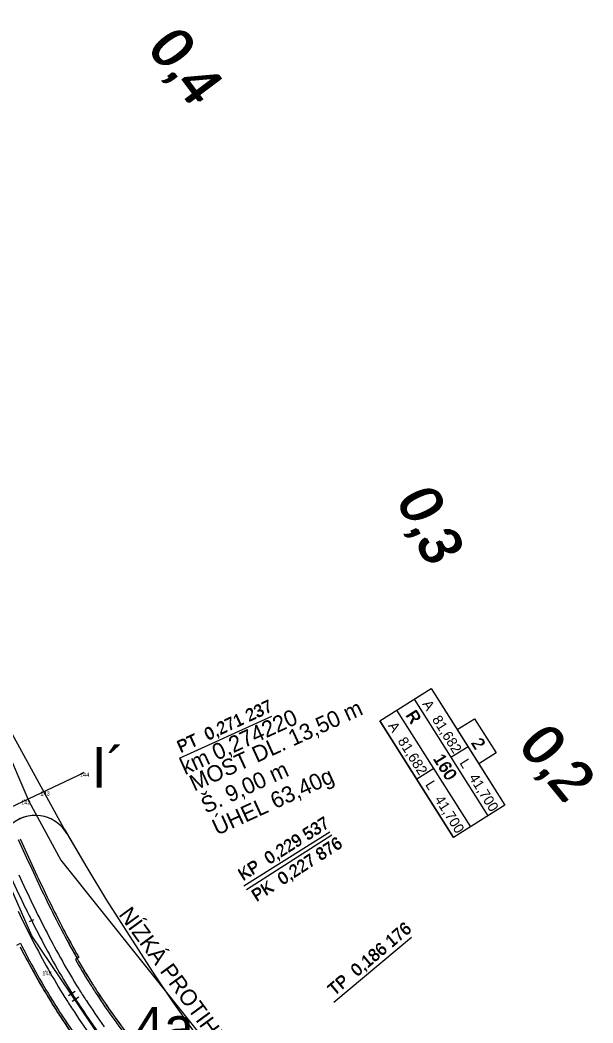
# Model space of a CAD drawing. Extents: x -606444 to -604546, y -1158114 to -1156869.
# Drawn here: x -605105.4 to -604964.2, y -1157370.5 to -1157123.3 of the extents above; entities that cross this region are included whole.
import ezdxf

# ---------------------------------------------------------------- set-up
doc = ezdxf.new("R2010")
doc.units = 0
for name, color, linetype in [('B_TRAM', 7, 'Continuous'), ('B_VOZ', 7, 'Continuous'), ('B_ZELEN', 7, 'Continuous'), ('geofyzikální profily_předběžný GTP', 7, 'Continuous'), ('NS_VB', 7, 'Continuous'), ('NS_VB_OBJ', 7, 'Continuous'), ('NS_VB_POP', 7, 'Continuous'), ('OSA', 7, 'Continuous'), ('OSAPOP', 7, 'Continuous'), ('podélný profil trasou tramvaje', 7, 'Continuous'), ('Sondy 2', 7, 'Continuous'), ('stabilitní profily_předběžný GTP', 7, 'Continuous')]:
    doc.layers.add(name, color=color, linetype=linetype)

msp = doc.modelspace()

# ---------------------------------------------------------------- linework, layer by layer
for p, q in [((-605089.73, -1157308.8), (-605089.83, -1157308.7)), ((-605089.73, -1157308.8), (-605089.83, -1157308.9)), ((-605089.73, -1157308.8), (-605089.63, -1157308.7)), ((-605089.73, -1157308.8), (-605089.63, -1157308.9)), ((-605099.46, -1157313.42), (-605099.56, -1157313.32)), ((-605099.46, -1157313.42), (-605099.56, -1157313.52)), ((-605099.46, -1157313.42), (-605099.36, -1157313.32)), ((-605099.46, -1157313.42), (-605099.36, -1157313.52)), ((-605104.19, -1157315.62), (-605104.29, -1157315.52)), ((-605104.19, -1157315.62), (-605104.29, -1157315.72)), ((-605104.19, -1157315.62), (-605104.09, -1157315.52)), ((-605104.19, -1157315.62), (-605104.09, -1157315.72)), ((-605099, -1157357.72), (-605099.1, -1157357.62)), ((-605099, -1157357.72), (-605099.1, -1157357.82)), ((-605099, -1157357.72), (-605098.9, -1157357.62)), ((-605099, -1157357.72), (-605098.9, -1157357.82))]:
    msp.add_line(p, q)
at = {"layer": 'B_TRAM'}
for centre, radius, start, end in [((-603789.87, -1156724.37), 1446.67, 204.54292, 204.85878), ((-604698.87, -1157145.52), 444.85, 204.8588, 205.8756), ((-604812.37, -1157200.57), 318.71, 205.8756, 207.2908), ((-604908.16, -1157249.99), 210.91, 207.2908, 209.4068), ((-604908.16, -1157249.99), 221.91, 207.2908, 209.4068), ((-604937.73, -1157266.66), 176.97, 209.4068, 211.9219), ((-604937.73, -1157266.66), 187.97, 209.4068, 211.9219), ((-604973.31, -1157288.82), 135.05, 211.9219, 213.2869), ((-604929.75, -1157260.22), 187.17, 213.2869, 215.6693), ((-604973.31, -1157288.82), 146.05, 211.9219, 213.2869), ((-604929.75, -1157260.22), 198.17, 213.2869, 215.6693), ((-604901.68, -1157240.08), 221.71, 215.6693, 217.6844)]:
    msp.add_arc(centre, radius, start, end, dxfattribs=at)
at = {"layer": 'B_VOZ'}
for points in [[(-605094.5, -1157322.63), (-605109.17, -1157295.78)], [(-605093.83, -1157323.78), (-605094.5, -1157322.63)]]:
    msp.add_lwpolyline(points, dxfattribs=at)
msp.add_arc((-605101.6, -1157328.32), 9, 30.3498, 133.794, dxfattribs=at)
at = {"layer": 'B_ZELEN'}
for p, q in [((-605093.83, -1157323.78), (-605088.92, -1157332.16)), ((-605088.92, -1157332.16), (-605084.06, -1157340.17)), ((-605084.06, -1157340.17), (-605072.72, -1157357.89)), ((-605072.72, -1157357.89), (-605067.87, -1157365.11)), ((-605067.87, -1157365.11), (-605057.63, -1157379.5))]:
    msp.add_line(p, q, dxfattribs=at)
for centre, radius, start, end in [((-605101.6, -1157328.32), 9, 30.3498, 121.5185), ((-604385.24, -1156998.22), 791.34, 204.4121, 204.98957), ((-604559.79, -1157079.57), 598.77, 204.98957, 205.74572), ((-604856.99, -1157222.9), 268.81, 205.7457, 207.422), ((-604881.9, -1157235.82), 240.75, 207.422, 209.2775), ((-604910.99, -1157251.45), 218.7, 207.2752, 209.4223), ((-604952.19, -1157275.23), 160.17, 209.2775, 212.0497), ((-605101.63, -1157358.96), 0.164, 29.3533, 29.4223), ((-604944.33, -1157270.5), 180.3, 209.3533, 211.9753), ((-604934.17, -1157263.95), 181.43, 212.0497, 212.5556), ((-604971.94, -1157288.06), 136.62, 212.5556, 213.2436), ((-604935.66, -1157264.28), 179.99, 213.2436, 215.7168), ((-604962.84, -1157282.05), 158.48, 211.9753, 213.2335), ((-604936.77, -1157264.97), 189.65, 213.2335, 215.7228), ((-604892.9, -1157233.53), 232.66, 215.7168, 217.6392)]:
    msp.add_arc(centre, radius, start, end, dxfattribs=at)
at = {"layer": 'geofyzikální profily_předběžný GTP'}
msp.add_lwpolyline([(-605670.78, -1157141.05), (-605656.02, -1157139.47), (-605613.88, -1157139.36), (-605584.8, -1157137.32), (-605531.41, -1157136.33), (-605491.56, -1157133.4), (-605482.07, -1157135.61), (-605438.78, -1157126.66), (-605383.23, -1157124.52), (-605352.34, -1157123.33), (-605321.95, -1157126), (-605284.14, -1157130.42), (-605243.3, -1157142.6), (-605207.83, -1157158.83), (-605179.98, -1157186.15), (-605165.29, -1157202.67), (-605149.23, -1157223.34), (-605135.07, -1157244.47), (-605115.92, -1157286.28), (-605103.22, -1157315.84), (-605095.33, -1157330.32), (-605036.97, -1157403.36), (-604999.08, -1157442.54), (-604970.8, -1157468.35)], dxfattribs=at)
at = {"layer": 'NS_VB'}
for p, q in [((-605094.5, -1157322.63), (-605109.17, -1157295.78)), ((-605094.5, -1157322.63), (-605088.92, -1157332.16)), ((-605093.83, -1157323.78), (-605094.5, -1157322.63)), ((-605088.92, -1157332.16), (-605084.06, -1157340.17)), ((-605084.06, -1157340.17), (-605072.72, -1157357.89)), ((-605072.72, -1157357.89), (-605067.87, -1157365.11)), ((-605072.72, -1157357.89), (-605067.87, -1157365.11)), ((-605067.87, -1157365.11), (-605057.63, -1157379.5))]:
    msp.add_line(p, q, dxfattribs=at)
msp.add_lwpolyline([(-605090.87, -1157354.36), (-605091.74, -1157354.85)], dxfattribs=at)
for centre, radius, start, end in [((-605101.6, -1157328.32), 9, 30.3498, 133.794), ((-604045.75, -1156842.07), 1165.02, 204.50489, 204.89659), ((-604665.75, -1157129.81), 481.51, 204.8966, 205.8378), ((-604827.34, -1157208.06), 301.97, 205.8378, 207.3286), ((-604900.92, -1157246.08), 219.15, 207.3286, 209.369), ((-604900.92, -1157246.08), 230.15, 207.3286, 209.369), ((-604942.46, -1157269.46), 171.48, 209.369, 211.9582), ((-604942.46, -1157269.46), 171.98, 209.7708, 211.9583), ((-604942.46, -1157269.46), 182.48, 209.369, 211.9596), ((-604956.93, -1157278.34), 155, 212.0055, 212.5997), ((-604956.93, -1157278.34), 154.5, 212.0056, 212.5997), ((-604954.13, -1157276.54), 158.33, 212.6018, 213.1974), ((-604954.13, -1157276.54), 157.83, 212.6018, 213.1974), ((-604935.79, -1157264.37), 180.33, 213.2425, 215.7151), ((-604935.79, -1157264.37), 179.83, 213.2425, 215.7151), ((-604956.93, -1157278.34), 165.5, 212.004, 212.5997), ((-604954.13, -1157276.54), 168.83, 212.6017, 213.1988), ((-604935.79, -1157264.37), 190.83, 213.2412, 215.7151), ((-604892.8, -1157233.46), 232.79, 215.7151, 217.6387), ((-604892.8, -1157233.46), 233.29, 215.7151, 217.6387)]:
    msp.add_arc(centre, radius, start, end, dxfattribs=at)
at = {"layer": 'NS_VB_OBJ'}
msp.add_lwpolyline([(-605106.18, -1157351.28), (-605105.29, -1157350.82)], dxfattribs=at)
for centre, radius, start, end in [((-604045.75, -1156842.07), 1164.52, 204.50488, 204.89659), ((-604665.75, -1157129.81), 481.01, 204.8966, 205.8378), ((-604827.34, -1157208.06), 301.47, 205.8378, 207.3286), ((-604900.92, -1157246.08), 218.65, 207.3286, 209.369), ((-604827.34, -1157208.06), 312.47, 207.1861, 207.3286), ((-604900.92, -1157246.08), 229.65, 207.3286, 209.369), ((-604942.46, -1157269.46), 170.98, 209.369, 209.7708), ((-604942.46, -1157269.46), 181.98, 209.369, 211.9596), ((-604956.93, -1157278.34), 165, 212.004, 212.5997), ((-604954.13, -1157276.54), 168.33, 212.6017, 213.1988), ((-604935.79, -1157264.37), 190.33, 213.2413, 215.7151)]:
    msp.add_arc(centre, radius, start, end, dxfattribs=at)
at = {"layer": 'OSA'}
for centre, radius, start, end in [((-604665.75, -1157129.81), 487.01, 204.8966, 205.8378), ((-604665.75, -1157129.81), 485.01, 204.8966, 205.8378), ((-604827.34, -1157208.06), 307.47, 205.8378, 207.3286), ((-604827.34, -1157208.06), 305.47, 205.8378, 207.3286), ((-604827.34, -1157208.06), 309.47, 205.8378, 207.3286), ((-604900.92, -1157246.08), 224.65, 207.3286, 209.369), ((-604900.92, -1157246.08), 222.65, 207.3286, 209.369), ((-604900.92, -1157246.08), 226.65, 207.3286, 209.369), ((-604942.46, -1157269.46), 176.98, 209.369, 211.9589), ((-604942.46, -1157269.46), 174.98, 209.369, 211.9587), ((-604942.46, -1157269.46), 178.98, 209.369, 211.9592), ((-604956.93, -1157278.34), 162, 212.0045, 212.5997), ((-604956.93, -1157278.34), 160, 212.0047, 212.5997), ((-604956.93, -1157278.34), 158, 212.005, 212.5997), ((-604954.13, -1157276.54), 161.33, 212.6018, 213.1979), ((-604954.13, -1157276.54), 165.33, 212.6018, 213.1984), ((-604954.13, -1157276.54), 163.33, 212.6018, 213.1981), ((-604935.79, -1157264.37), 185.33, 213.2419, 215.7151), ((-604935.79, -1157264.37), 183.33, 213.2421, 215.7151), ((-604935.79, -1157264.37), 187.33, 213.2416, 215.7151)]:
    msp.add_arc(centre, radius, start, end, dxfattribs=at)
at = {"layer": 'OSAPOP'}
for p, q in [((-605004.05, -1157288.02), (-604997.64, -1157298.16)), ((-605008.28, -1157290.69), (-604990.11, -1157319.43)), ((-605066.06, -1157305.25), (-605043.32, -1157294.87)), ((-604994.33, -1157322.1), (-605012.5, -1157293.36)), ((-605016.73, -1157296.03), (-604998.56, -1157324.77)), ((-604997.64, -1157298.16), (-604992.29, -1157306.61)), ((-604994.97, -1157302.39), (-604999.19, -1157305.06)), ((-604992.29, -1157306.61), (-604985.88, -1157316.76)), ((-605003.42, -1157307.73), (-605007.64, -1157310.4)), ((-605050.21, -1157336.64), (-605029.01, -1157323.39)), ((-605049.6, -1157337.6), (-605028.54, -1157324.13)), ((-605103.05, -1157345.5), (-605101.97, -1157344.97)), ((-605028.05, -1157365.38), (-605008.91, -1157349.29)), ((-605093.46, -1157363.67), (-605091.76, -1157362.61)), ((-605092.57, -1157365.08), (-605090.88, -1157364))]:
    msp.add_line(p, q, dxfattribs=at)
msp.add_lwpolyline([(-605004.05, -1157288.02), (-604985.88, -1157316.76), (-604998.56, -1157324.77), (-605016.73, -1157296.03)], close=True, dxfattribs=at)
msp.add_lwpolyline([(-604997.64, -1157298.16), (-604993.41, -1157295.49), (-604988.07, -1157303.94), (-604992.29, -1157306.61)], dxfattribs=at)
at = {"layer": 'podélný profil trasou tramvaje'}
msp.add_lwpolyline([(-605085.67, -1157373.96), (-605102.48, -1157348.99), (-605137.42, -1157269.35), (-605142.94, -1157257.48), (-605148.09, -1157246.14), (-605156.56, -1157230.62), (-605167.27, -1157214.45), (-605176.96, -1157202.08), (-605190.28, -1157187.63), (-605201.93, -1157176.87), (-605210.19, -1157170.25), (-605214.51, -1157166.83), (-605234.53, -1157153.68), (-605243.13, -1157148.91), (-605255.42, -1157142.97), (-605270.4, -1157136.88), (-605273.54, -1157135.89), (-605289.22, -1157131.03), (-605304.97, -1157127.5), (-605318.55, -1157125.25), (-605341.87, -1157123.88), (-605358.23, -1157124.22), (-605590.31, -1157143.82)], dxfattribs=at)
at = {"layer": 'stabilitní profily_předběžný GTP'}
msp.add_lwpolyline([(-605133.4, -1157329.44), (-605089.73, -1157308.8)], dxfattribs=at)

# ---------------------------------------------------------------- texts
for s, p in [('144', (-605090.63, -1157309.8)), ('143', (-605100.36, -1157314.42)), ('142', (-605105.09, -1157316.62)), ('148', (-605099.9, -1157358.72))]:
    msp.add_text(s, height=1).set_placement(p)
at = {"layer": 'NS_VB_POP'}
for s, rotation, p in [('MOST DL. 13,50 m', 24.5384, (-605062.46, -1157313.46)), ('km 0,274220', 24.5384, (-605064.73, -1157309.43)), ('Š. 9,00 m', 24.5384, (-605059.63, -1157318.94)), ('ÚHEL 63,40g', 24.5384, (-605056.85, -1157324.34)), ('NÍZKÁ PROTIHLUKOVÁ STĚNA DL. 46,00 m', 306.1505, (-605081.23, -1157343.77)), ('NÍZKÁ PROTIHLUKOVÁ STĚNA DL. 56,00 m', 305.0864, (-605120.47, -1157361.33))]:
    msp.add_text(s, height=4, rotation=rotation, dxfattribs=at).set_placement(p)
at = {"layer": 'OSAPOP'}
for s, height, rotation, p in [('0,4', 10, 307.0102, (-605074.36, -1157130.18)), ('0,4', 10, 307.0102, (-605074.15, -1157130.21)), ('0,4', 10, 307.0102, (-605073.94, -1157130.24)), ('0,4', 10, 307.0102, (-605073.73, -1157130.27)), ('0,3', 10, 294.5384, (-605012.83, -1157241.27)), ('0,3', 10, 294.5384, (-605012.63, -1157241.34)), ('0,3', 10, 294.5384, (-605012.43, -1157241.42)), ('0,3', 10, 294.5384, (-605012.23, -1157241.49)), ('PT  0,271 237', 3, 24.5384, (-605065.84, -1157304.05)), ('PT  0,271 237', 3, 24.5384, (-605065.77, -1157303.85)), ('A', 2.5, 302.3022, (-605006.34, -1157291.87)), ('R', 3, 302.3022, (-605010.54, -1157294.6)), ('R', 3, 302.3022, (-605010.33, -1157294.65)), ('81,682', 2.5, 302.3022, (-605003.95, -1157295.66)), ('A', 2.5, 302.3022, (-605014.8, -1157297.22)), ('0,2', 10, 309.2455, (-604982.99, -1157302.18)), ('0,2', 10, 309.2455, (-604982.78, -1157302.2)), ('0,2', 10, 309.2455, (-604982.57, -1157302.23)), ('0,2', 10, 309.2455, (-604982.36, -1157302.25)), ('81,682', 2.5, 302.3022, (-605012.41, -1157301)), ('2', 3, 302.3022, (-604994.39, -1157301.43)), ('2', 3, 302.3022, (-604994.18, -1157301.48)), ('160', 3, 302.3022, (-605003.77, -1157305.31)), ('160', 3, 302.3022, (-605003.56, -1157305.35)), ('L', 2.5, 302.3022, (-604997.17, -1157306.38)), ('41,700', 2.5, 302.3022, (-604994.87, -1157310.02)), ('L', 2.5, 302.3022, (-605005.62, -1157311.73)), ('41,700', 2.5, 302.3022, (-605003.32, -1157315.37)), ('KP  0,229 537', 3, 32.0047, (-605050.44, -1157335.6)), ('KP  0,229 537', 3, 32.0047, (-605050.4, -1157335.4)), ('PK  0,227 876', 3, 32.5997, (-605047.11, -1157340.76)), ('PK  0,227 876', 3, 32.5997, (-605047.06, -1157340.55)), ('TP  0,186 176', 3, 40.0661, (-605027.96, -1157364)), ('TP  0,186 176', 3, 40.0661, (-605027.95, -1157363.79))]:
    msp.add_text(s, height=height, rotation=rotation, dxfattribs=at).set_placement(p)
at = {"layer": 'Sondy 2'}
msp.add_text('4a', height=10, dxfattribs=at).set_placement((-605077.37, -1157376.5))
at = {"layer": 'stabilitní profily_předběžný GTP'}
msp.add_text('I´', height=10, dxfattribs=at).set_placement((-605087.73, -1157312.48))

doc.saveas('drawing.dxf')
